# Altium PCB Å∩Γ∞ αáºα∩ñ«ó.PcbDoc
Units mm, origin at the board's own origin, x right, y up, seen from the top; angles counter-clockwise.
Board outline 100 x 65 mm, 2 copper layers (Top Layer, Bottom Layer); 171 components, 171 nets, 507 pads, 41 vias.
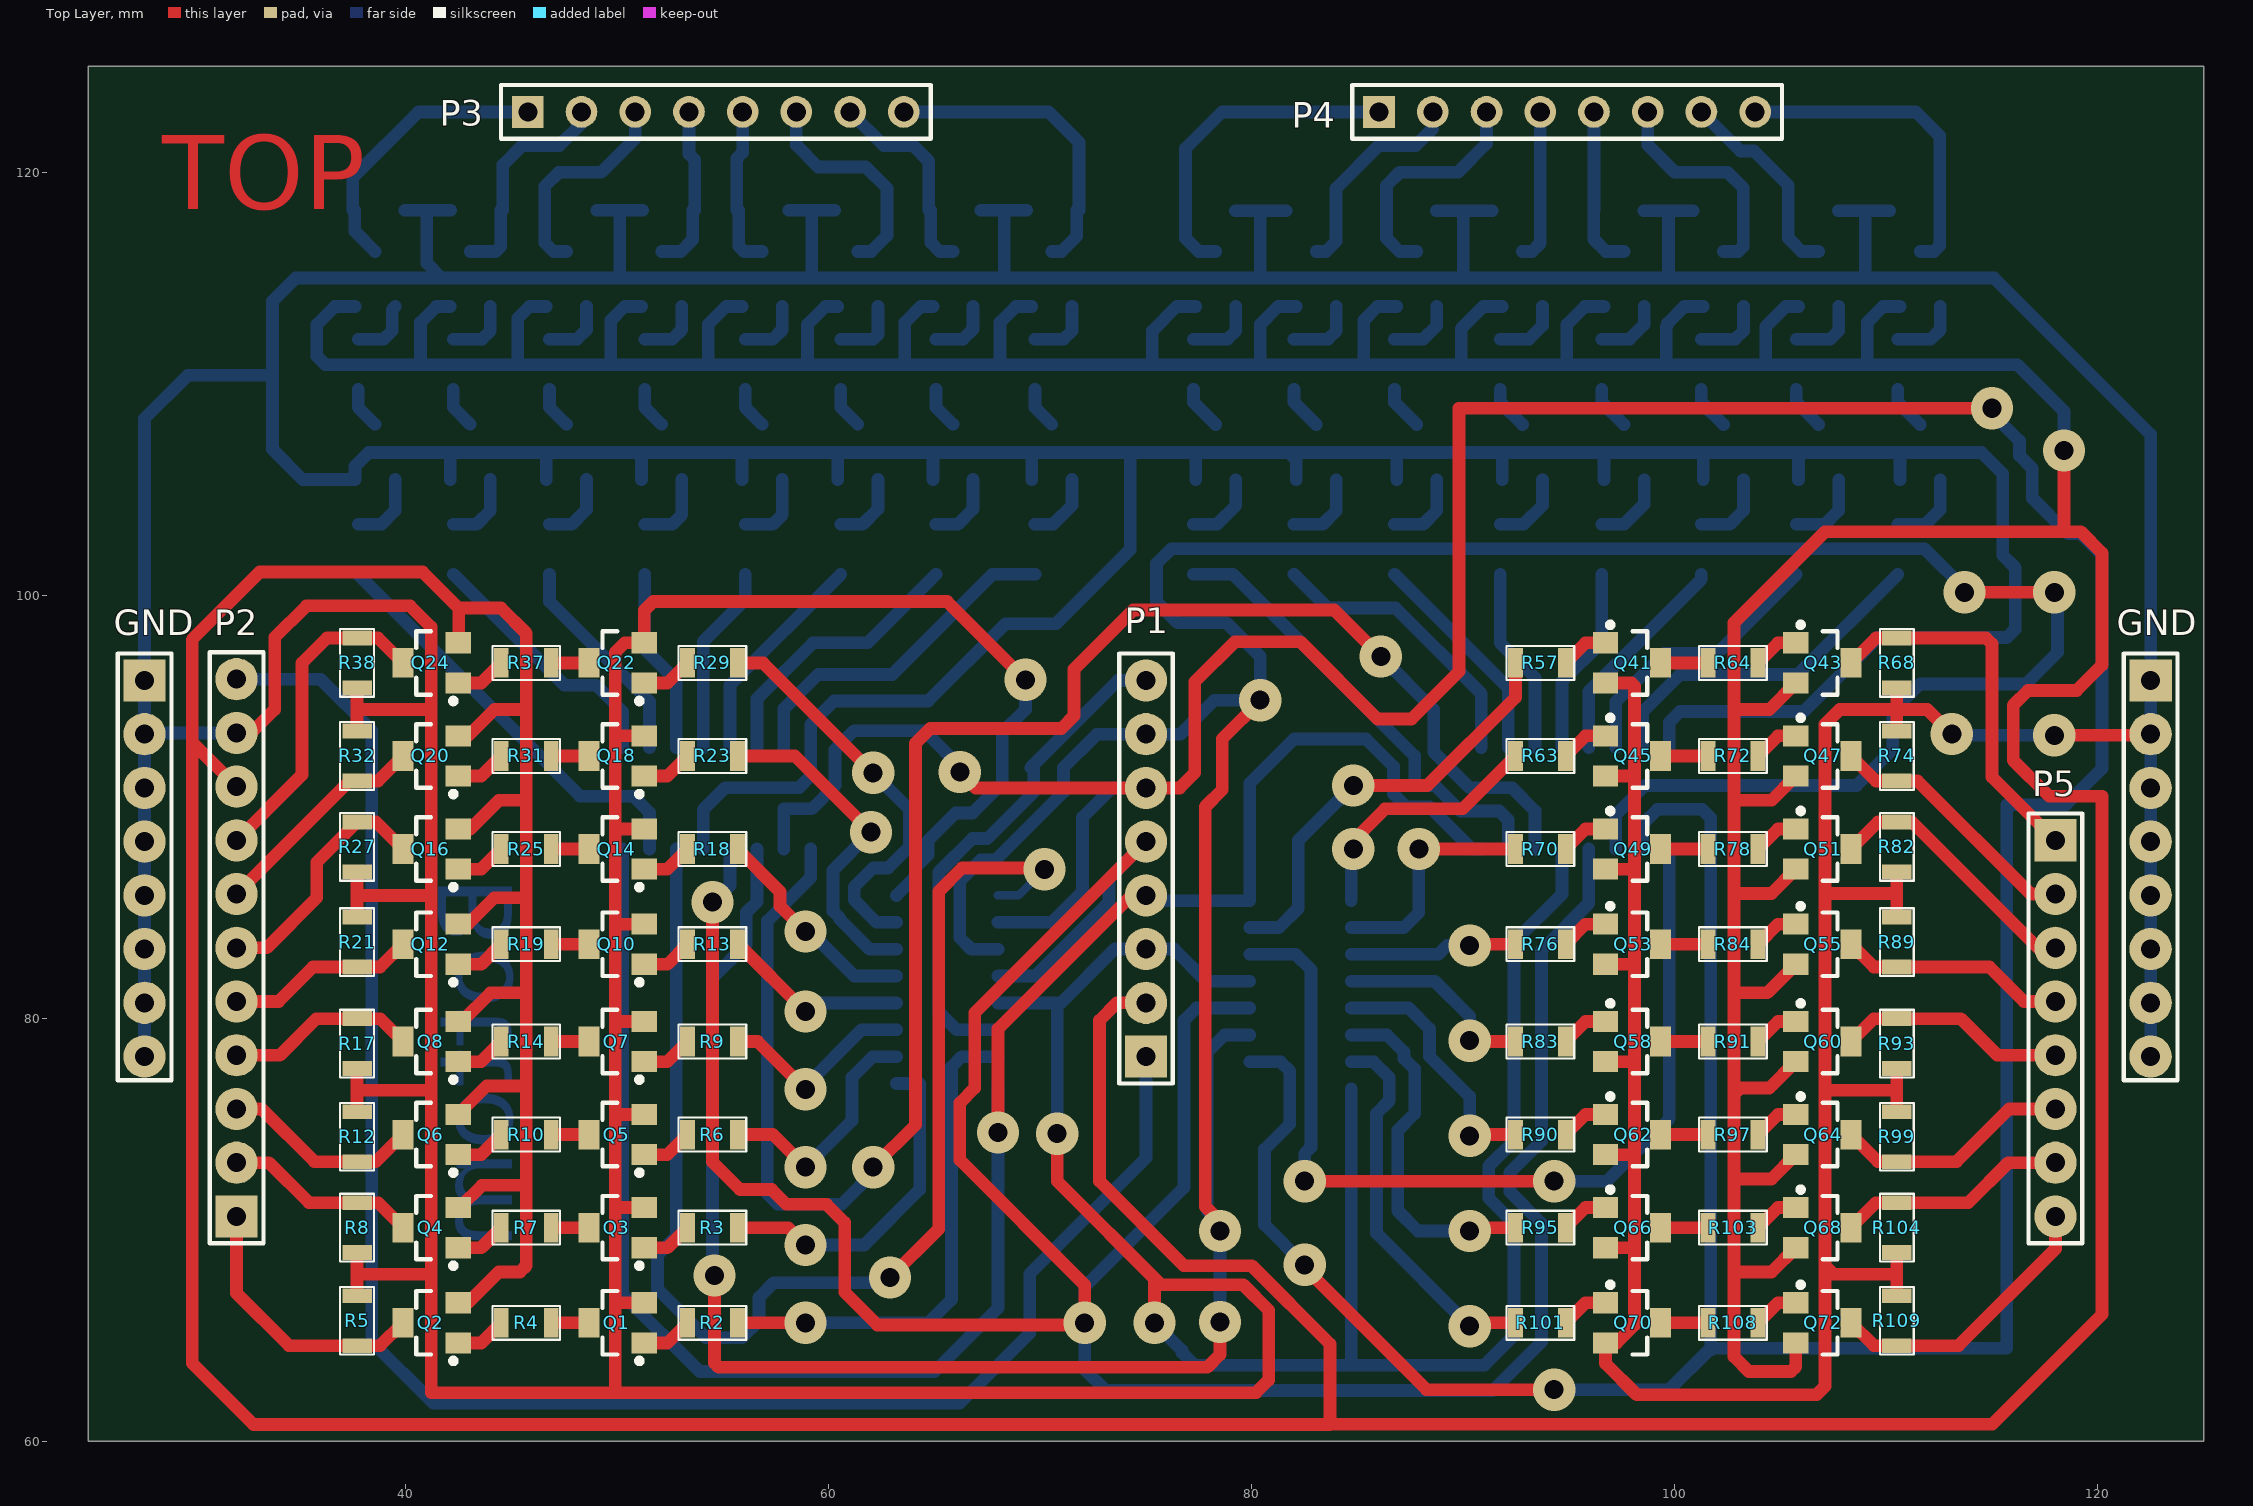
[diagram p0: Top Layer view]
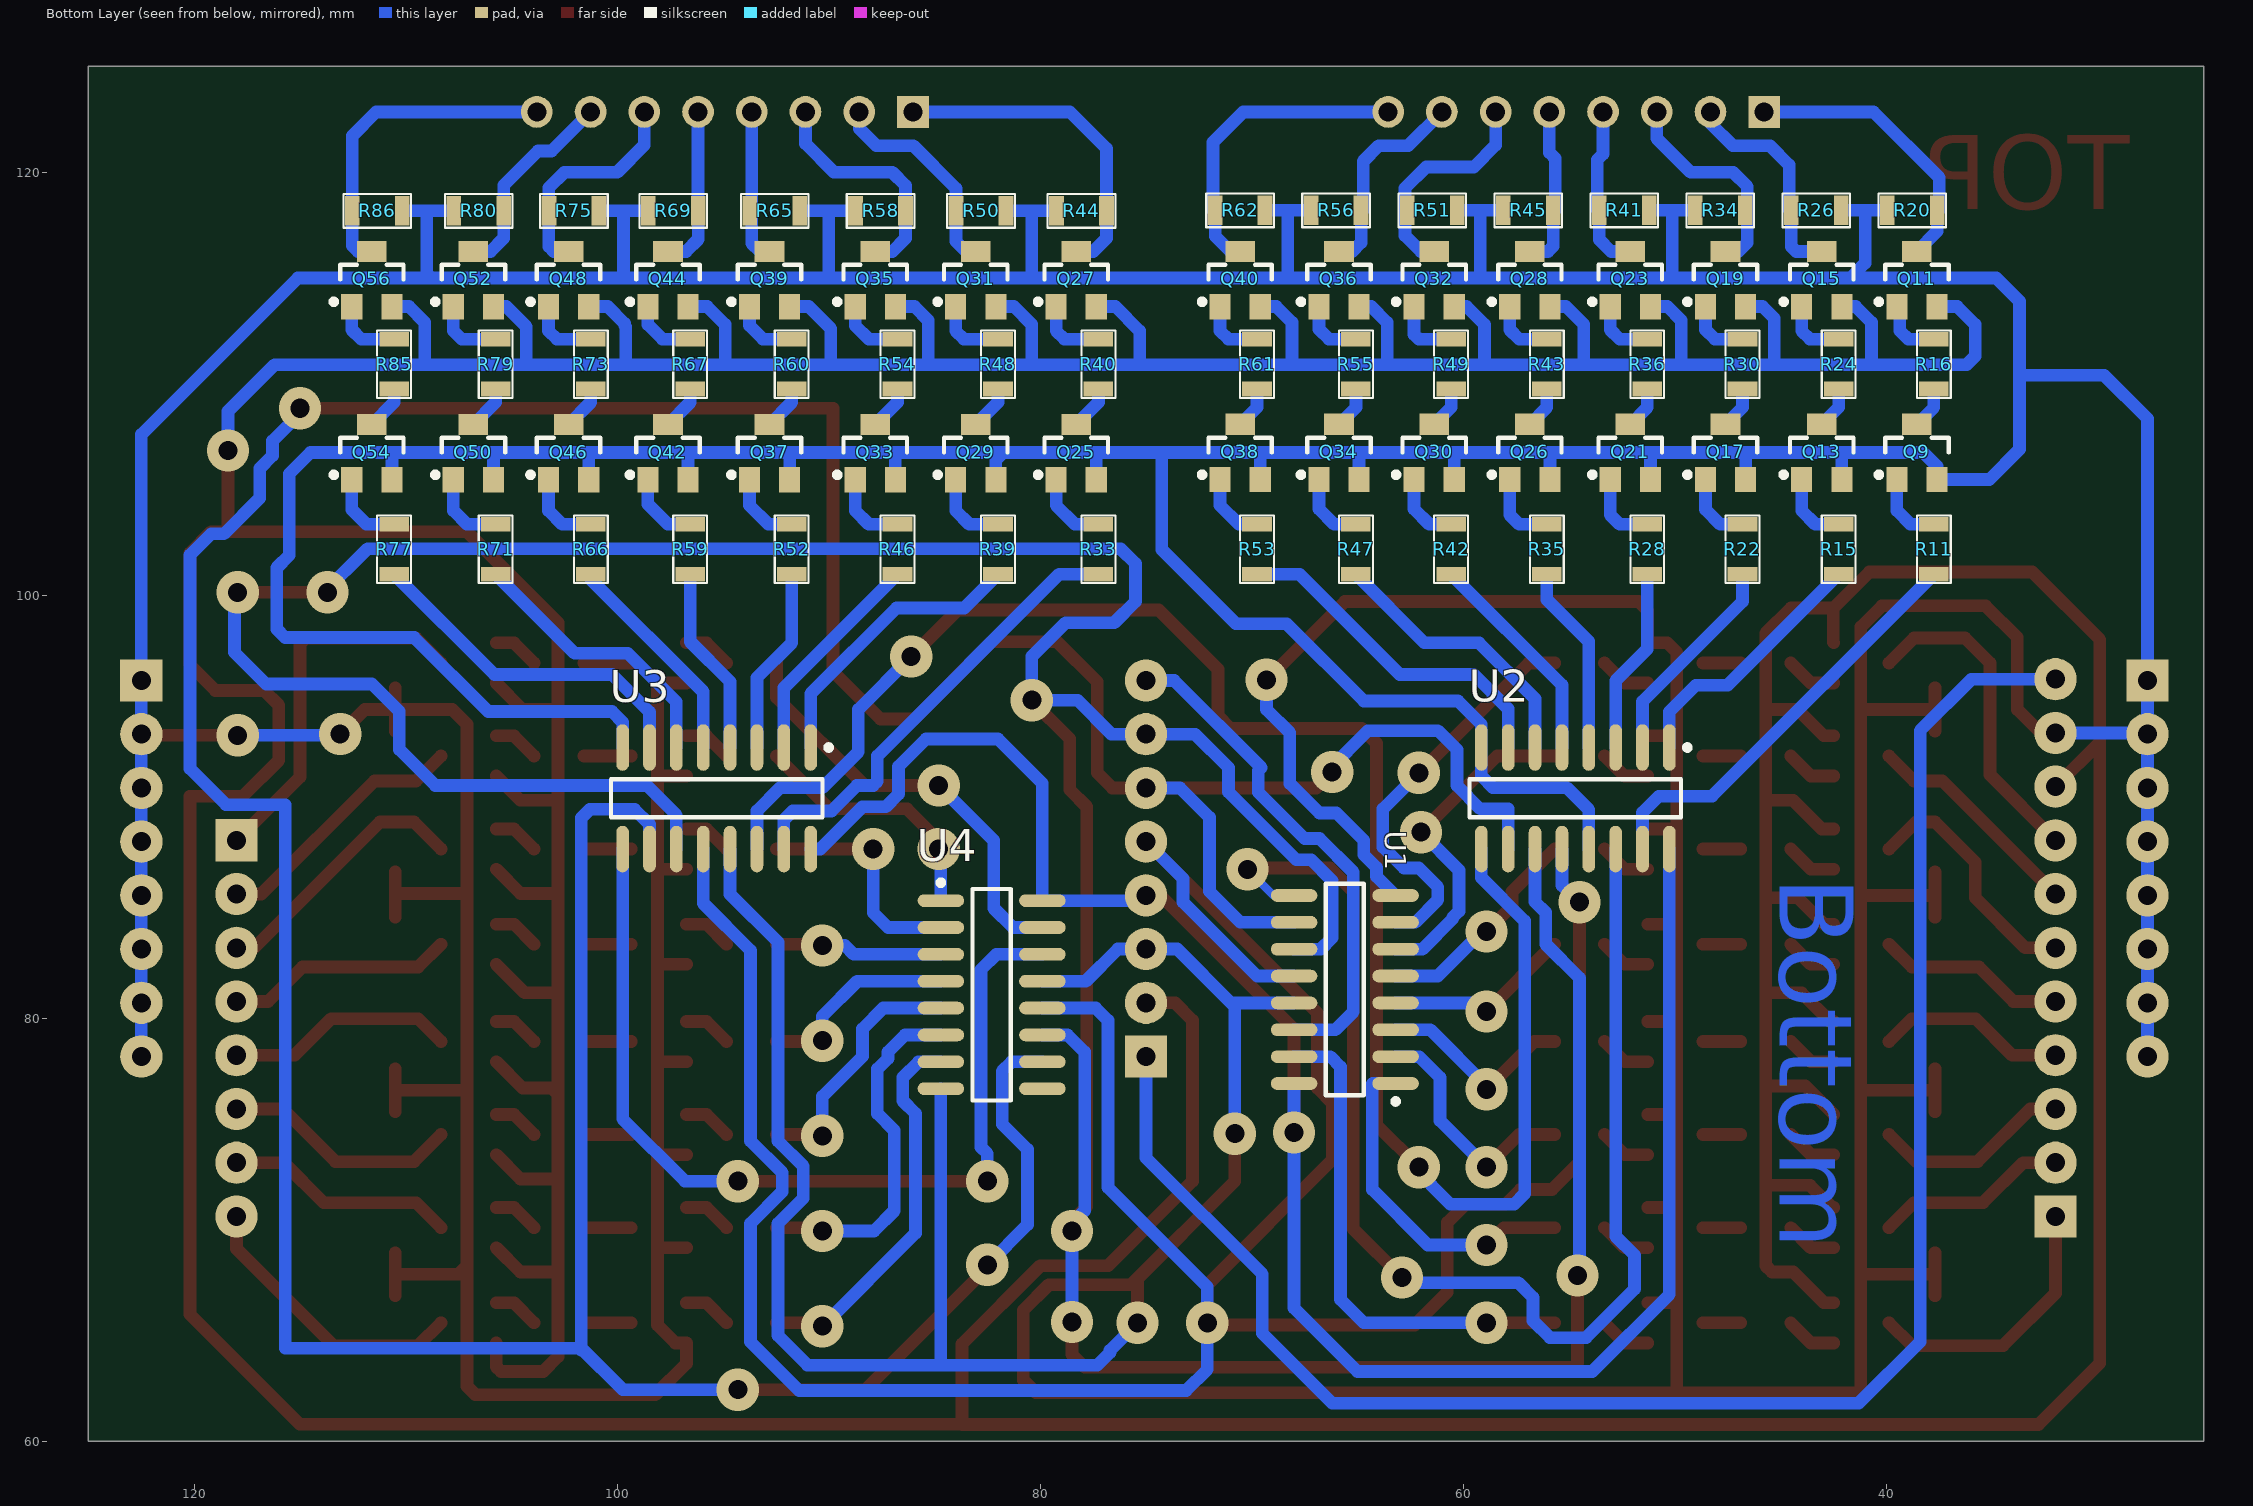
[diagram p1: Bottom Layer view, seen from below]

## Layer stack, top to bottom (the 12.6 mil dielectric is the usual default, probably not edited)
Top Solder: solder mask 0.0102, Solder Resist, Dk 3.5
Top Layer: signal copper 0.0356
Dielectric 1: dielectric 0.32, FR-4, Dk 4.8
Bottom Layer: signal copper 0.0356
Bottom Solder: solder mask 0.0102, Solder Resist, Dk 3.5

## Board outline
25,125 25,60 125,60 125,125

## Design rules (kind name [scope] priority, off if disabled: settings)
Clearance [All] p1: gap=0.3 ignorepadtopadclearanceinfootprint=FALSE except(0: Arc-Hole Track-Hole SMDPad-Hole THPad-Hole Via-Hole Fill-Hole Poly-Hole Region-Hole Text-Hole)
PolygonConnect [All] p1: connectstyle=Relief reliefconductorwidth=0.254 reliefentries=4 polygonreliefangle="90 Angle" airgapwidth=0.254
RoutingVias [All] p1: holewidth=0.711 width=1.27 viastyle="Through Hole" minholewidth=0.711 minwidth=1.27 maxholewidth=0.711 maxwidth=1.27
SolderMaskExpansion [All] p1: expansion=0.102
Width [All] p1: maxlimit=1 minlimit=0.4 preferedwidth=0.4 minimp=50.000000 maximp=50.000000 favimp=50.000000
30 further rules are at their usual default settings.

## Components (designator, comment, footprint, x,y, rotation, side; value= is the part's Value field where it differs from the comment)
GND "8pin" 8PIN 27.65,95.97 r270 top (schematic designator P3)
GND "8pin" 8PIN 122.5,95.97 r270 top (schematic designator P3)
P1 "Ещё порты" HDR1X8#1 75,78.19 r90 top
P2 "Ещё порты" HDR_X11 32,70.63 r90 top
P3 "Ещё порты" HDR1X8#2 45.77,122.85 r0 top
P4 "Ещё порты" HDR1X8#2 86.02,122.85 r0 top
P5 "Ещё порты" HDR1X8#1 118,88.41 r270 top
Q1 "2SC2712" SOT23_N 50,65.6 r180 top
Q2 "2SA1162" SOT23_N 41.2,65.6 r180 top
Q3 "2SC2712" SOT23_N 50,70.1 r180 top
Q4 "2SA1162" SOT23_N 41.2,70.1 r180 top
Q5 "2SC2712" SOT23_N 50,74.5 r180 top
Q6 "2SA1162" SOT23_N 41.2,74.5 r180 top
Q7 "2SC2712" SOT23_N 50,78.9 r180 top
Q8 "2SA1162" SOT23_N 41.2,78.9 r180 top
Q9 "2SC2712" SOT23_N 38.55,106.75 r90 bottom
Q10 "2SC2712" SOT23_N 50,83.5 r180 top
Q11 "2SA1162" SOT23_N 38.55,114.925 r90 bottom
Q12 "2SA1162" SOT23_N 41.2,83.5 r180 top
Q13 "2SC2712" SOT23_N 43.05,106.75 r90 bottom
Q14 "2SC2712" SOT23_N 50,88 r180 top
Q15 "2SA1162" SOT23_N 43.05,114.925 r90 bottom
Q16 "2SA1162" SOT23_N 41.2,88 r180 top
Q17 "2SC2712" SOT23_N 47.6,106.75 r90 bottom
Q18 "2SC2712" SOT23_N 50,92.4 r180 top
Q19 "2SA1162" SOT23_N 47.6,114.925 r90 bottom
Q20 "2SA1162" SOT23_N 41.2,92.4 r180 top
Q21 "2SC2712" SOT23_N 52.1,106.75 r90 bottom
Q22 "2SC2712" SOT23_N 50,96.8 r180 top
Q23 "2SA1162" SOT23_N 52.1,114.925 r90 bottom
Q24 "2SA1162" SOT23_N 41.2,96.8 r180 top
Q25 "2SC2712" SOT23_N 78.3,106.744 r90 bottom
Q26 "2SC2712" SOT23_N 56.85,106.75 r90 bottom
Q27 "2SA1162" SOT23_N 78.3,114.925 r90 bottom
Q28 "2SA1162" SOT23_N 56.85,114.925 r90 bottom
Q29 "2SC2712" SOT23_N 83.05,106.744 r90 bottom
Q30 "2SC2712" SOT23_N 61.375,106.75 r90 bottom
Q31 "2SA1162" SOT23_N 83.05,114.925 r90 bottom
Q32 "2SA1162" SOT23_N 61.375,114.925 r90 bottom
Q33 "2SC2712" SOT23_N 87.8,106.744 r90 bottom
Q34 "2SC2712" SOT23_N 65.875,106.75 r90 bottom
Q35 "2SA1162" SOT23_N 87.8,114.925 r90 bottom
Q36 "2SA1162" SOT23_N 65.875,114.925 r90 bottom
Q37 "2SC2712" SOT23_N 92.8,106.744 r90 bottom
Q38 "2SC2712" SOT23_N 70.55,106.75 r90 bottom
Q39 "2SA1162" SOT23_N 92.8,114.925 r90 bottom
Q40 "2SA1162" SOT23_N 70.55,114.925 r90 bottom
Q41 "2SC2712" SOT23_N 98,96.8 r0 top
Q42 "2SC2712" SOT23_N 97.6,106.744 r90 bottom
Q43 "2SA1162" SOT23_N 107,96.8 r0 top
Q44 "2SA1162" SOT23_N 97.6,114.925 r90 bottom
Q45 "2SC2712" SOT23_N 98,92.4 r0 top
Q46 "2SC2712" SOT23_N 102.3,106.744 r90 bottom
Q47 "2SA1162" SOT23_N 107,92.4 r0 top
Q48 "2SA1162" SOT23_N 102.3,114.925 r90 bottom
Q49 "2SC2712" SOT23_N 98,88 r0 top
Q50 "2SC2712" SOT23_N 106.8,106.744 r90 bottom
Q51 "2SA1162" SOT23_N 107,88 r0 top
Q52 "2SA1162" SOT23_N 106.8,114.925 r90 bottom
Q53 "2SC2712" SOT23_N 98,83.5 r0 top
Q54 "2SC2712" SOT23_N 111.6,106.744 r90 bottom
Q55 "2SA1162" SOT23_N 107,83.5 r0 top
Q56 "2SA1162" SOT23_N 111.6,114.925 r90 bottom
Q58 "2SC2712" SOT23_N 98,78.9 r0 top
Q60 "2SA1162" SOT23_N 107,78.9 r0 top
Q62 "2SC2712" SOT23_N 98,74.5 r0 top
Q64 "2SA1162" SOT23_N 107,74.5 r0 top
Q66 "2SC2712" SOT23_N 98,70.1 r0 top
Q68 "2SA1162" SOT23_N 107,70.1 r0 top
Q70 "2SC2712" SOT23_N 98,65.6 r0 top
Q72 "2SA1162" SOT23_N 107,65.6 r0 top
R2 "1k" 6-0805_N 54.5,65.6 r180 top
R3 "1k" 6-0805_N 54.5,70.1 r180 top
R4 "22k" 6-0805_N 45.7,65.6 r0 top
R5 "3k" 6-0805_N 37.7,65.7 r90 top
R6 "1k" 6-0805_N 54.5,74.5 r180 top
R7 "22k" 6-0805_N 45.7,70.1 r0 top
R8 "3k" 6-0805_N 37.7,70.1 r270 top
R9 "1k" 6-0805_N 54.5,78.9 r180 top
R10 "22k" 6-0805_N 45.7,74.5 r0 top
R11 "1k" 6-0805_N 37.75,102.175 r90 bottom
R12 "3k" 6-0805_N 37.7,74.4 r90 top
R13 "1k" 6-0805_N 54.5,83.5 r180 top
R14 "3k" 6-0805_N 45.7,78.9 r0 top
R15 "1k" 6-0805_N 42.25,102.175 r90 bottom
R16 "22k" 6-0805_N 37.75,110.925 r270 bottom
R17 "22k" 6-0805_N 37.7,78.8 r270 top
R18 "1k" 6-0805_N 54.5,88 r180 top
R19 "22k" 6-0805_N 45.7,83.5 r0 top
R20 "3k" 6-0805_N 38.769,118.2 r0 bottom
R21 "3k" 6-0805_N 37.7,83.6 r90 top
R22 "1k" 6-0805_N 46.8,102.175 r90 bottom
R23 "1k" 6-0805_N 54.5,92.4 r180 top
R24 "22k" 6-0805_N 42.25,110.925 r270 bottom
R25 "22k" 6-0805_N 45.7,88 r0 top
R26 "3k" 6-0805_N 43.309,118.2 r180 bottom
R27 "3k" 6-0805_N 37.7,88.1 r270 top
R28 "1k" 6-0805_N 51.3,102.175 r90 bottom
R29 "1k" 6-0805_N 54.5,96.8 r180 top
R30 "22k" 6-0805_N 46.8,110.925 r270 bottom
R31 "22k" 6-0805_N 45.7,92.4 r0 top
R32 "3k" 6-0805_N 37.7,92.4 r90 top
R33 "1k" 6-0805_N 77.25,102.175 r90 bottom
R34 "3k" 6-0805_N 47.849,118.2 r0 bottom
R35 "1k" 6-0805_N 56.05,102.175 r90 bottom
R36 "22k" 6-0805_N 51.3,110.925 r270 bottom
R37 "22k" 6-0805_N 45.7,96.8 r0 top
R38 "3k" 6-0805_N 37.7,96.8 r270 top
R39 "1k" 6-0805_N 82,102.175 r90 bottom
R40 "22k" 6-0805_N 77.25,110.925 r270 bottom
R41 "3k" 6-0805_N 52.389,118.2 r180 bottom
R42 "1k" 6-0805_N 60.575,102.175 r90 bottom
R43 "22k" 6-0805_N 56.05,110.925 r270 bottom
R44 "3k" 6-0805_N 78.05,118.175 r0 bottom
R45 "3k" 6-0805_N 56.93,118.2 r0 bottom
R46 "1k" 6-0805_N 86.75,102.175 r90 bottom
R47 "1k" 6-0805_N 65.075,102.175 r90 bottom
R48 "22k" 6-0805_N 82,110.925 r270 bottom
R49 "22k" 6-0805_N 60.575,110.925 r270 bottom
R50 "3k," 6-0805_N 82.8,118.175 r180 bottom
R51 "3k" 6-0805_N 61.47,118.2 r180 bottom
R52 "1k" 6-0805_N 91.75,102.175 r90 bottom
R53 "1k" 6-0805_N 69.75,102.175 r90 bottom
R54 "22k" 6-0805_N 86.75,110.925 r270 bottom
R55 "22k" 6-0805_N 65.075,110.925 r270 bottom
R56 "3k" 6-0805_N 66.01,118.2 r0 bottom
R57 "1k" 6-0805_N 93.65,96.8 r0 top
R58 "3k" 6-0805_N 87.55,118.175 r0 bottom
R59 "1k" 6-0805_N 96.55,102.175 r90 bottom
R60 "22k" 6-0805_N 91.75,110.925 r270 bottom
R61 "22k" 6-0805_N 69.75,110.925 r270 bottom
R62 "3k" 6-0805_N 70.55,118.2 r180 bottom
R63 "1k" 6-0805_N 93.65,92.4 r0 top
R64 "22k" 6-0805_N 102.75,96.8 r180 top
R65 "3k" 6-0805_N 92.55,118.175 r180 bottom
R66 "1k" 6-0805_N 101.25,102.175 r90 bottom
R67 "22k" 6-0805_N 96.55,110.925 r270 bottom locked
R68 "3k" 6-0805_N 110.5,96.8 r270 top
R69 "3k" 6-0805_N 97.35,118.175 r0 bottom
R70 "1k" 6-0805_N 93.65,88 r0 top
R71 "1k" 6-0805_N 105.75,102.175 r90 bottom
R72 "22k" 6-0805_N 102.75,92.4 r180 top
R73 "22k" 6-0805_N 101.25,110.925 r270 bottom
R74 "3k" 6-0805_N 110.5,92.4 r90 top
R75 "3k" 6-0805_N 102.05,118.175 r180 bottom
R76 "1k" 6-0805_N 93.65,83.5 r0 top
R77 "1k" 6-0805_N 110.55,102.175 r90 bottom
R78 "22k" 6-0805_N 102.75,88 r180 top
R79 "22k" 6-0805_N 105.75,110.925 r270 bottom
R80 "3k" 6-0805_N 106.55,118.175 r0 bottom
R82 "3k" 6-0805_N 110.5,88.1 r270 top
R83 "1k" 6-0805_N 93.65,78.9 r0 top
R84 "22k" 6-0805_N 102.75,83.5 r180 top
R85 "22k" 6-0805_N 110.55,110.925 r270 bottom
R86 "3k" 6-0805_N 111.35,118.175 r180 bottom
R89 "3k" 6-0805_N 110.5,83.6 r90 top
R90 "1k" 6-0805_N 93.65,74.5 r0 top
R91 "22k" 6-0805_N 102.75,78.9 r180 top
R93 "3k" 6-0805_N 110.5,78.8 r270 top
R95 "1k" 6-0805_N 93.65,70.1 r0 top
R97 "22k" 6-0805_N 102.75,74.5 r180 top
R99 "22k" 6-0805_N 110.5,74.4 r90 top
R101 "1k" 6-0805_N 93.65,65.6 r0 top
R103 "22k" 6-0805_N 102.75,70.1 r180 top
R104 "3k" 6-0805_N 110.5,70.1 r270 top
R108 "22k" 6-0805_N 102.75,65.6 r180 top
R109 "3k" 6-0805_N 110.5,65.7 r90 top
U1 "SN74HC595D" D016_N 65.6,81.36 r0 bottom
U2 "SN74HC595D" D016_N 54.7,90.4 r270 bottom
U3 "SN74HC595D" D016_N 95.3,90.4 r270 bottom
U4 "SN74HC595D" D016_N 82.3,81.115 r180 bottom

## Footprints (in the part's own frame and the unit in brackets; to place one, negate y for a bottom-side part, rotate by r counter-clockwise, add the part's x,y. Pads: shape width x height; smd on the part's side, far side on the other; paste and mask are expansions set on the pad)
6-0805_N [mm]
  rect 0.7x1.4 smd: 1(-1.181,0) 2(1.181,0)
  silkscreen extent -1.6,-0.8 1.6,0.8, body extent -1.07,-0.7 1.07,0.7, height 0.7
8PIN [mm] "Connector; Header; 4 Position"
  rect 2x2 hole 0.9: 1(0,0)
  round 2 hole 0.9: 2(2.54,0) 3(5.08,0) 4(7.62,0) 5(10.16,0) 6(12.7,0) 7(15.24,0) 8(17.78,0)
  silkscreen extent -1.27,-1.27 18.9,1.27
D016_N [mm]
  oval 2.2x0.6 smd: 1(-2.4,4.445) 2(-2.4,3.175) 3(-2.4,1.905) 4(-2.4,0.635) 5(-2.4,-0.635) 6(-2.4,-1.905) 7(-2.4,-3.175) 8(-2.4,-4.445) 9(2.4,-4.445) 10(2.4,-3.175) 11(2.4,-1.905) 12(2.4,-0.635) 13(2.4,0.635) 14(2.4,1.905) 15(2.4,3.175) 16(2.4,4.445)
  silkscreen extent -2.52,-5 0.9,5.42, body extent -1.95,-4.95 1.95,4.95, height 1.75
HDR1X8#1 [mm] "Connector; Header; 8 Position"
  rect 2x2 hole 0.9: 1(0,0)
  round 2 hole 0.9: 2(2.54,0) 3(5.08,0) 4(7.62,0) 5(10.16,0) 6(12.7,0) 7(15.24,0) 8(17.78,0)
  silkscreen extent -1.27,-1.27 19.05,1.27
HDR1X8#2 [mm] "Connector; Header; 8 Position"
  rect 1.5x1.5 hole 0.9: 1(0,0)
  round 1.5 hole 0.9: 2(2.54,0) 3(5.08,0) 4(7.62,0) 5(10.16,0) 6(12.7,0) 7(15.24,0) 8(17.78,0)
  silkscreen extent -1.27,-1.27 19.05,1.27
HDR_X11 [mm] "Connector; Header; 11 Position"
  rect 2x2 hole 0.9: 1(0,0)
  round 2 hole 0.9: 2(2.54,0) 3(5.08,0) 4(7.62,0) 5(10.16,0) 6(12.7,0) 7(15.24,0) 8(17.78,0) 9(20.32,0) 10(22.86,0) 11(25.4,0)
  silkscreen extent -1.27,-1.27 26.67,1.27
SOT23_N [mm]
  rect 1.2x1 smd: 1(-1.277,0.95) 2(-1.277,-0.95)
  rect 1x1.4 smd: 3(1.331,0)
  silkscreen extent -1.18,-1.5 0.7,1.92, body extent -0.7,-1.5 0.7,1.5, height 1.1

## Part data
P1 P3 P4 P5: library part "Header 9", "Header, 9-Pin"
P2: library part "Header 11", "Header, 11-Pin"
Q1 Q3 Q5 Q7 Q9 Q10 Q13 Q14 Q17 Q18 Q21 Q22 Q25 Q26 Q29 Q30 Q33 Q34 Q37 Q38 Q41 Q42 Q45 Q46 Q49 Q50 Q53 Q54 Q58 Q62 Q66 Q70: "NPN"
Q2 Q4 Q6 Q8 Q11 Q12 Q15 Q16 Q19 Q20 Q23 Q24 Q27 Q28 Q31 Q32 Q35 Q36 Q39 Q40 Q43 Q44 Q47 Q48 Q51 Q52 Q55 Q56 Q60 Q64 Q68 Q72: "PNP"
R5 R8 R12 R14 R20 R21 R26 R27 R32 R34 R38 R41 R44 R45 R50 R51 R56 R58 R62 R65 R68 R69 R74 R75 R80 R82 R86 R89 R93 R104 R109: library part 22k, "22k"
U1 U2 U3 U4: "8-Bit Shift Register with 3-State Output Registers"

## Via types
v1: diameter 2, hole 0.9, Top Layer to Bottom Layer, 41 vias

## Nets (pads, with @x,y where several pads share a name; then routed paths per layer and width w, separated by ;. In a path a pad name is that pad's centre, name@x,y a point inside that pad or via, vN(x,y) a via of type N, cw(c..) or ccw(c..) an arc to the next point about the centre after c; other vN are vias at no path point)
30V: P1.2 P2.9 Q2.2 Q4.2 Q6.2 Q8.2 Q11.2 Q12.2 Q15.2 Q16.2 Q19.2 Q20.2 Q23.2 Q24.2 Q27.2 Q28.2 Q31.2 Q32.2 Q35.2 Q36.2 Q39.2 Q40.2 Q43.2 Q44.2 Q47.2 Q48.2 Q51.2 Q52.2 Q55.2 Q56.2 Q60.2 Q64.2 Q68.2 Q72.2 | length 511.3
  Top Layer w0.6: P2.9 29.9,93.05 ; Q2.2 42.95,66.55 44.4,68 45.4,68 45.7,68.3 45.7,72.1 ; Q4.2 42.55,71.05 43.6,72.1 45.7,72.1 ; Q6.2 43.827,76.8 45.7,76.8 ; Q8.2 42.65,79.85 44,81.2 45.7,81.2 ; Q12.2 42.95,84.45 44.2,85.7 45.7,85.7 ; Q16.2 43.05,88.95 44.4,90.3 45.7,90.3 ; Q20.2 42.95,93.35 44.2,94.6 45.7,94.6 ; Q24.2 42.5,97.773 42.5,99.4 ; P1.2 73.63,80.73 72.8,79.9 72.8,72.3 76.8,68.3 80,68.3 83.7,64.6 83.7,60.8 ; Q72.2 105.723,63.523 105.5,63.3 103.5,63.3 102.8,64 102.8,68 ; Q68.2 104.573,68 102.8,68 ; Q64.2 104.573,72.4 102.8,72.4 ; Q60.2 104.473,76.7 103.1,76.7 102.8,76.4 ; Q55.2 104.373,81.2 102.8,81.2 ; Q51.2 104.573,85.9 102.8,85.9 ; Q47.2 104.573,90.3 102.8,90.3 ; Q43.2 104.473,94.6 102.8,94.6 ; v1(118.4,106.84) 118.4,103 ; 29.9,93.05 29.9,97.9 33.1,101.1 40.8,101.1 42.5,99.4 ; 29.9,93.05 29.9,63.7 32.806,60.794 83.7,60.794 83.7,60.8 ; 42.5,99.4 44.5,99.4 45.7,98.2 45.7,94.6 ; 45.7,72.1 45.7,76.8 ; 45.7,76.8 45.7,81.2 ; 45.7,81.2 45.7,85.7 ; 45.7,85.7 45.7,90.3 ; 45.7,90.3 45.7,94.6 ; 83.7,60.8 115,60.8 120.2,66 120.2,90.5 117.7,90.5 116,92.2 116,94.8 116.7,95.5 119,95.5 120.2,96.7 120.2,102 119.2,103 118.4,103 ; 102.8,68 102.8,72.4 ; 102.8,72.4 102.8,76.4 ; 102.8,76.4 102.8,81.2 ; 102.8,81.2 102.8,85.9 ; 102.8,85.9 102.8,90.3 ; 102.8,90.3 102.8,94.6 ; 102.8,94.6 102.8,98.7 107.1,103 118.4,103
  Bottom Layer w0.6: Q11.2 36.648,113.648 35.8,112.8 35.8,111.3 36.2,110.9 40.7,110.9 ; Q15.2 41.448,113.648 40.7,112.9 40.7,110.9 ; Q19.2 45.848,113.648 45.3,113.1 45.3,110.9 ; Q23.2 50.348,113.648 49.7,113 49.7,110.9 ; Q28.2 55.148,113.648 54.3,112.8 54.3,110.9 ; Q32.2 59.848,113.648 59,112.8 59,110.9 ; Q36.2 64.348,113.648 63.6,112.9 63.6,110.9 ; Q40.2 68.848,113.648 68.1,112.9 68.1,110.9 ; Q27.2 76.448,113.648 75.3,112.5 75.3,110.9 ; Q31.2 81.248,113.648 80.4,112.8 80.4,110.9 ; Q35.2 85.948,113.648 85.3,113 85.3,110.9 ; Q39.2 90.948,113.648 89.9,112.6 89.9,110.9 ; Q44.2 95.748,113.648 94.9,112.8 94.9,110.9 ; Q48.2 100.448,113.648 99.65,112.85 99.65,112.749 99.6,112.699 99.6,110.9 ; Q52.2 105.248,113.648 104.3,112.7 104.3,110.9 ; Q56.2 109.848,113.648 109.1,112.9 109.1,110.9 ; v1(118.4,106.84) 118.4,108.7 116.2,110.9 109.1,110.9 ; 40.7,110.9 45.3,110.9 ; 45.3,110.9 49.7,110.9 ; 49.7,110.9 54.3,110.9 ; 54.3,110.9 59,110.9 ; 59,110.9 63.6,110.9 ; 63.6,110.9 68.1,110.9 ; 68.1,110.9 75.3,110.9 ; 75.3,110.9 80.4,110.9 ; 80.4,110.9 85.3,110.9 ; 85.3,110.9 89.9,110.9 ; 89.9,110.9 94.9,110.9 ; 94.9,110.9 99.6,110.9 ; 99.6,110.9 104.3,110.9 ; 104.3,110.9 109.1,110.9
Glow_1: P1.1 P2.11 | length 85.3
  Bottom Layer w0.6: P2.11 35.97,96.03 38.4,93.6 38.4,64.7 41.3,61.8 66.2,61.8 69.5,65.1 69.5,67.9 75,73.4 P1.1
Glow_2: GND.1 GND.2 GND.3 GND.4 GND.5 GND.6 GND.7 GND.8 P1.3 P2.10 Q1.2 Q3.2 Q5.2 Q7.2 Q9.2 Q10.2 Q13.2 Q14.2 Q17.2 Q18.2 Q21.2 Q22.2 Q25.2 Q26.2 Q29.2 Q30.2 Q33.2 Q34.2 Q37.2 Q38.2 Q41.2 Q42.2 Q45.2 Q46.2 Q49.2 Q50.2 Q53.2 Q54.2 Q58.2 Q62.2 Q66.2 Q70.2 R5.2 R8.2 R12.2 R17.2 R20.2 R21.2 R26.2 R27.2 R32.2 R34.2 R38.2 R41.2 R44.2 R45.2 R50.2 R51.2 R56.2 R58.2 R62.2 R65.2 R68.2 R69.2 R74.2 R75.2 R80.2 R82.2 R86.2 R89.2 R93.2 R99.2 R104.2 R109.2 U1.8 U1.13 U2.8 U2.13 U3.8 U3.13 U4.8 U4.13 | length 787.8
  Top Layer w0.6: P2.10 32.69,93.49 33.8,94.6 33.8,98 35.3,99.5 40.2,99.5 41.2,98.5 41.2,85.8 ; R5.2 37.7,67.9 ; R8.2 37.7,67.9 ; R12.2 37.7,76.6 ; R17.2 37.7,76.6 ; R21.2 37.7,85.85 ; R27.2 37.7,85.85 ; R32.2 37.7,94.6 ; R38.2 37.7,94.6 ; 41.1,94.6 37.7,94.6 ; Q1.2 50.05,66.55 49.9,66.4 ; Q3.2 49.95,71.05 49.9,71.1 ; Q5.2 49.95,75.45 49.9,75.4 ; Q7.2 49.95,79.85 49.9,79.9 ; Q10.2 49.95,84.45 49.9,84.5 ; Q14.2 49.95,88.95 49.9,88.9 ; Q18.2 49.95,93.35 49.9,93.4 ; v1(69.3,96) 65.6,99.7 51.7,99.7 51.277,99.277 Q22.2 50.35,97.75 49.9,97.3 49.9,93.4 ; v1@70.8,74.5 70.8,72.3 75.7,67.4 79.6,67.4 80.8,66.2 80.8,62.9 80.2,62.3 49.9,62.3 ; v1(75.4,65.6) 75.4,67.6 ; Q66.2 97.95,69.15 98.1,69 ; Q62.2 98.05,73.55 98.1,73.6 ; Q58.2 98.05,77.95 98.1,77.9 ; Q53.2 98.05,82.55 98.1,82.5 ; Q49.2 98.05,87.05 98.1,87.1 ; Q45.2 98.05,91.45 98.1,91.4 ; Q41.2 97.95,95.85 98.1,95.7 98.1,91.4 ; R109.2 110.5,67.9 ; R104.2 110.5,67.9 ; R99.2 110.5,76.6 ; R93.2 110.5,76.6 ; R89.2 110.5,85.9 ; R82.2 110.5,85.9 ; R74.2 110.5,94.6 ; R68.2 110.5,94.6 ; v1(113.1,93.44) 111.94,94.6 110.5,94.6 ; v1(117.944,93.374) 122.444,93.374 GND.2@122.5,93.43 ; 37.7,67.9 41.1,67.9 41.2,68 ; 37.7,76.6 41.2,76.6 ; 37.7,85.85 37.75,85.8 41.2,85.8 ; 41.2,68 41.2,62.3 49.9,62.3 ; 41.2,68 41.2,76.6 ; 41.2,76.6 41.2,85.8 ; 49.9,62.3 49.9,66.4 ; 49.9,66.4 49.9,71.1 ; 49.9,71.1 49.9,75.4 ; 49.9,75.4 49.9,79.9 ; 49.9,79.9 49.9,84.5 ; 49.9,84.5 49.9,88.9 ; 49.9,88.9 49.9,93.4 ; 98.1,69 98.1,73.6 ; 98.1,69 98.1,65.5 97.25,64.65 Q70.2 96.723,63.677 98.2,62.2 106.7,62.2 107.1,62.6 107.1,68.3 ; 98.1,73.6 98.1,77.9 ; 98.1,77.9 98.1,82.5 ; 98.1,82.5 98.1,87.1 ; 98.1,87.1 98.1,91.4 ; 107.1,68.3 107.1,76.6 ; 107.1,68.3 107.5,67.9 110.5,67.9 ; 107.1,76.6 107.1,85.9 ; 107.1,76.6 110.5,76.6 ; 107.1,85.9 107.1,93.9 107.8,94.6 110.5,94.6 ; 107.1,85.9 110.5,85.9
  Bottom Layer w0.6: GND.8@27.65,78.19 27.65,80.73 27.65,83.27 27.65,85.81 27.65,88.35 27.65,90.89 GND.2@27.65,93.43 ; P2.10 27.71,93.49 GND.2@27.65,93.43 ; R20.2 41,118.2 ; Q13.2 42.1,106.6 42.25,106.75 ; R26.2 41,118.2 ; Q17.2 46.65,106.65 46.75,106.75 ; R34.2 50.119,118.2 ; Q21.2 51.15,106.6 51,106.75 ; R41.2 50.119,118.2 ; U2.13 54.065,89.865 55.1,90.9 58.6,90.9 59.145,91.445 U2.8 59.145,93.895 60.25,95 64.7,95 68.35,98.65 70.75,98.65 74.25,102.15 74.25,106.75 ; Q26.2 55.9,106.65 56,106.75 ; R45.2 59.2,118.2 ; R51.2 59.2,118.2 ; Q30.2 60.425,106.675 60.5,106.75 ; U1.8 64.1,86.705 64.1,87.127 64.7,87.727 64.7,88.4 66,89.7 66.8,89.7 68.2,91.1 68.2,93.5 69.3,94.6 v1@69.3,95.8 ; Q34.2 64.925,106.575 64.75,106.75 ; R56.2 68.3,118.2 ; U1.13 70.975,80.725 ; R62.2 68.3,118.2 ; Q38.2 69.6,106.65 69.5,106.75 ; v1(70.8,74.54) 70.8,80.55 70.975,80.725 ; v1(75.4,65.6) 76.7,64.3 76.7,64.2 77.3,63.6 84.9,63.6 ; Q25.2 77.35,106.6 77.5,106.75 ; R44.2 80.4,118.175 ; U4.13 77.85,81.75 76.33,83.27 P1.3 73.52,83.27 70.975,80.725 ; R50.2 80.4,118.175 ; Q29.2 82.1,106.4 81.75,106.75 ; U4.8 84.7,63.8 84.9,63.6 ; Q33.2 86.85,106.6 87,106.75 ; R58.2 90,118.175 ; R65.2 90,118.175 ; Q37.2 91.85,106.6 92,106.75 ; U3.13 94.665,85.865 92.4,83.6 92.4,74.2 91.2,73 91.2,71.5 92.4,70.3 92.4,65 91,63.6 84.9,63.6 ; Q42.2 96.65,106.6 96.5,106.75 ; R69.2 99.7,118.175 ; U3.8 99.745,93.995 100.25,94.5 106.1,94.5 109.6,98 115.7,98 116.1,98.4 116.1,101.3 115.5,101.9 115.5,105.75 114.5,106.75 110.5,106.75 ; R75.2 99.7,118.175 ; Q46.2 101.35,106.65 101.25,106.75 ; Q50.2 105.85,106.6 106,106.75 ; R80.2 109,118.175 ; R86.2 109,118.175 ; Q54.2 110.65,106.6 110.5,106.75 ; v1@113.3,93.374 v1(117.944,93.374) ; GND.8@122.5,78.19 122.5,80.73 122.5,83.27 122.5,85.81 122.5,88.35 122.5,90.89 122.5,93.43 122.5,95.97 122.5,107.6 115.1,115 108.8,115 ; GND.2@27.65,93.43 27.65,95.97 27.65,108.35 29.7,110.4 33.7,110.4 ; 33.7,110.4 33.7,113.9 34.8,115 41.7,115 ; 33.7,110.4 33.7,106.9 35.127,105.473 Q9.2 37.6,106.1 38.25,106.75 42.25,106.75 ; 41,118.2 41,115.7 41.7,115 ; 41.7,115 50.2,115 ; 42.25,106.75 46.75,106.75 ; 46.75,106.75 51,106.75 ; 50.119,118.2 50.119,115.081 50.2,115 ; 50.2,115 59.2,115 ; 51,106.75 56,106.75 ; 56,106.75 60.5,106.75 ; 59.2,115 68.3,115 ; 59.2,115 59.2,118.2 ; 60.5,106.75 64.75,106.75 ; 64.75,106.75 69.5,106.75 ; 68.3,115 80.3,115 ; 68.3,115 68.3,118.2 ; 69.5,106.75 74.25,106.75 ; 74.25,106.75 77.5,106.75 ; 77.5,106.75 81.75,106.75 ; 80.3,115 90,115 ; 80.3,115 80.4,115.1 80.4,118.175 ; 81.75,106.75 87,106.75 ; 87,106.75 92,106.75 ; 90,115 99.7,115 ; 90,115 90,118.175 ; 92,106.75 96.5,106.75 ; 96.5,106.75 101.25,106.75 ; 99.7,115 108.8,115 ; 99.7,115 99.7,118.175 ; 101.25,106.75 106,106.75 ; 106,106.75 110.5,106.75 ; 108.8,115 109,115.2 109,118.175
L1_A: P2.1 Q2.3 R5.1 | length 13
  Top Layer w0.6: P2.1 32,67 34.481,64.519 R5.1 38.788,64.519 Q2.3
L1_B: P2.2 Q4.3 R8.1 | length 9.1
  Top Layer w0.6: P2.2 33.53,73.17 35.419,71.281 R8.1 38.688,71.281 Q4.3
L1_C: P2.3 Q6.3 R12.1 | length 9.4
  Top Layer w0.6: P2.3 33.19,75.71 35.681,73.219 R12.1 38.588,73.219 Q6.3
L1_D: P2.4 Q8.3 R17.1 | length 9
  Top Layer w0.6: P2.4 34.05,78.25 35.781,79.981 R17.1 38.788,79.981 Q8.3
L1_E: P2.5 Q12.3 R21.1 | length 9
  Top Layer w0.6: P2.5 33.99,80.79 35.619,82.419 R21.1 38.788,82.419 Q12.3
L1_F: P2.6 Q16.3 R27.1 | length 11.8
  Top Layer w0.6: P2.6 33.43,83.33 35.8,85.7 35.8,87.381 R27.1 38.588,89.281 Q16.3
L1_G: P2.7 Q20.3 R32.1 | length 10.6
  Top Layer w0.6: P2.7 37.349,91.219 R32.1 38.688,91.219 Q20.3
L1_H: P2.8 Q24.3 R38.1 | length 15.4
  Top Layer w0.6: P2.8 35.1,91.51 35.1,96.8 36.281,97.981 R38.1 38.688,97.981 Q24.3
L2_A: P3.1 Q11.3 R20.1 | length 13.5
  Bottom Layer w0.6: R20.1@37.488,118.2 37.488,119.738 40.6,122.85 P3.1 ; R20.1 37.588,117.218 Q11.3
L2_B: P3.2 Q15.3 R26.1 | length 10.5
  Bottom Layer w0.6: Q15.3 44.256,116.256 44.49,116.49 R26.1 ; R26.1@44.59,118.2 44.59,120.34 45.5,121.25 47.25,121.25 48.31,122.31 P3.2
L2_C: P3.3 Q19.3 R34.1 | length 10.3
  Bottom Layer w0.6: Q19.3 46.994,116.256 46.568,116.682 46.568,119.318 47.25,120 49.25,120 50.85,121.6 P3.3
L2_D: P3.4 Q23.3 R41.1 | length 7.8
  Bottom Layer w0.6: Q23.3 53.006,116.256 53.57,116.82 R41.1 ; P3.4 53.39,120.86 53.67,120.58 R41.1@53.67,118.2
L2_E: P3.5 Q28.3 R45.1 | length 7.7
  Bottom Layer w0.6: R45.1@55.649,118.2 55.649,120.649 55.93,120.93 P3.5 ; R45.1 55.749,116.501 55.994,116.256 Q28.3
L2_F: P3.6 Q32.3 R51.1 | length 10.6
  Bottom Layer w0.6: P3.6 58.47,121.28 59.5,120.25 61.75,120.25 62.751,119.249 62.751,117.001 62.006,116.256 Q32.3
L2_G: P3.7 Q36.3 R56.1 | length 9.8
  Bottom Layer w0.6: P3.7 62.61,121.25 64,121.25 64.729,120.521 R56.1@64.729,118.2 ; R56.1 64.829,116.671 65.244,116.256 Q36.3
L2_H: P3.8 Q40.3 R62.1 | length 14.8
  Bottom Layer w0.6: P3.8 70.4,122.85 71.831,121.419 R62.1@71.831,118.2 ; Q40.3 71.006,116.256 71.731,116.981 R62.1
L3_A: P4.1 Q27.3 R44.1 | length 15.8
  Bottom Layer w0.6: Q27.3 77.494,116.256 76.869,116.881 R44.1 76.869,121.119 78.6,122.85 P4.1
L3_B: P4.2 Q31.3 R50.1 | length 10.2
  Bottom Layer w0.6: Q31.3 83.506,116.256 83.981,116.731 R50.1 83.981,119.231 86,121.25 87.75,121.25 88.56,122.06 P4.2
L3_C: P4.3 Q35.3 R58.1 | length 11.2
  Bottom Layer w0.6: Q35.3 86.994,116.256 86.369,116.881 R58.1 86.369,119.369 87,120 89.75,120 91.1,121.35 P4.3
L3_D: P4.4 Q39.3 R65.1 | length 7.2
  Bottom Layer w0.6: Q39.3 93.256,116.256 93.64,116.64 P4.4
L3_E: P4.5 Q44.3 R69.1 | length 7.7
  Bottom Layer w0.6: P4.5 96.18,118.186 R69.1 96.169,116.831 96.744,116.256 Q44.3
L3_F: P4.6 Q48.3 R75.1 | length 10.7
  Bottom Layer w0.6: P4.6 98.72,121.28 100,120 102.5,120 103.231,119.269 R75.1 103.231,116.481 103.006,116.256 Q48.3
L3_G: P4.7 Q52.3 R80.1 | length 9.7
  Bottom Layer w0.6: P4.7 103.11,121 103.75,121 105.369,119.381 R80.1 105.369,116.881 105.994,116.256 Q52.3
L3_H: P4.8 Q56.3 R86.1 | length 15.4
  Bottom Layer w0.6: P4.8 111.4,122.85 112.531,121.719 R86.1 112.531,116.531 112.256,116.256 Q56.3
L4_A: P5.1 Q43.3 R68.1 | length 17.8
  Top Layer w0.6: Q43.3 109.512,97.981 R68.1 114.719,97.981 115,97.7 115,91.41 P5.1
L4_B: P5.2 Q47.3 R74.1 | length 12.4
  Top Layer w0.6: Q47.3 109.512,91.219 R74.1 111.481,91.219 116.83,85.87 P5.2
L4_C: P5.3 Q51.3 R82.1 | length 12.7
  Top Layer w0.6: Q51.3 109.612,89.281 R82.1 111.219,89.281 117.17,83.33 P5.3
L4_D: P5.4 Q55.3 R89.1 | length 10.8
  Top Layer w0.6: Q55.3 109.412,82.419 R89.1 114.881,82.419 116.51,80.79 P5.4
L4_E: P5.5 Q60.3 R93.1 | length 10.8
  Top Layer w0.6: Q60.3 109.412,79.981 R93.1 113.519,79.981 115.25,78.25 P5.5
L4_F: P5.6 Q64.3 R99.1 | length 11.2
  Top Layer w0.6: Q64.3 109.612,73.219 R99.1 113.319,73.219 115.81,75.71 P5.6
L4_G: P5.7 Q68.3 R104.1 | length 10.9
  Top Layer w0.6: Q68.3 109.512,71.281 R104.1 113.881,71.281 115.77,73.17 P5.7
L4_H: P5.8 Q72.3 R109.1 | length 13.5
  Top Layer w0.6: Q72.3 109.412,64.519 R109.1 113.419,64.519 118,69.1 P5.8
NetP1_5: P1.5 U1.12 U2.12 U3.12 U4.12 | length 147.1
  Top Layer w0.6: v1@54.5,85.4 54.5,73.2 55.8,71.9 57.3,71.9 58,71.2 59.9,71.2 60.75,70.35 60.75,67.05 62.3,65.5 71.9,65.5 72.1,65.7 72.1,67.4 66.2,73.3 66.2,76 66.9,76.7 66.9,80.25 P1.5
  Bottom Layer w0.6: v1@54.5,85.44 55.335,86.275 U2.12 ; U1.12 69.745,81.995 73.25,85.5 73.25,86.6 P1.5 ; U4.12 77.38,80.48 76.8,79.9 76.8,72 72.1,67.3 72.1,63.4 73.1,62.4 91.4,62.4 93.7,64.7 93.7,70.3 92.2,71.8 92.2,72.7 93.7,74.2 93.7,83.2 95.935,85.435 U3.12
  other v1: 72.1,65.6 54.5,85.49
NetP1_6: P1.6 U1.10 U2.10 U3.10 U4.10 | length 224.2
  Top Layer w0.6: v1(66.2,91.64) 66.95,90.89 P1.6 76.59,90.89 77.3,91.6 77.3,95.9 79.2,97.8 82.3,97.8 85.95,94.15 87.55,94.15 89.8,96.4 89.8,108.84 v1(115,108.84) ; v1@82.4,67.9 82.8,67.9 88.26,62.44 v1(94.3,62.44)
  Bottom Layer w0.6: U2.10 57.875,89.9 59.2,89.9 60.3,91 60.3,92.7 61.2,93.6 64.5,93.6 v1@66.4,91.7 ; U1.10 70.535,84.535 72,86 72,89.5 73.39,90.89 P1.6 ; U4.10 81.36,77.94 81.8,77.5 81.8,75 80.6,73.8 80.6,70.24 v1(82.5,68.34) ; v1(94.3,62.44) 99.74,62.44 101.7,64.4 ; U3.10 98.475,89.175 99.175,89.875 101.3,89.875 101.7,89.475 101.7,64.4 ; 101.7,64.3 101.7,64.4 ; v1@114.8,108.8 116.3,107.3 116.3,106.6 116.9,106 116.9,104.6 118.6,102.9 119.2,102.9 120.2,101.9 120.2,91.8 118.5,90.1 115.7,90.1 115.7,64.4 101.7,64.4
NetP1_7: P1.7 U1.11 U2.11 U3.11 U4.11 | length 200.1
  Top Layer w0.6: v1(54.6,67.84) 54.6,63.7 54.8,63.5 77.9,63.5 78.5,64.1 v1(78.5,65.64) ; v1(78.5,69.94) 78.5,70.4 77.8,71.1 77.8,90 78.6,90.8 78.6,93.2 v1@80.4,95 ; v1(113.7,100.14) v1(117.944,100.14)
  Bottom Layer w0.6: v1@54.9,67.9 54.5,68.3 54.5,81.9 56.1,83.5 56.1,85 56.605,85.505 U2.11 ; U1.11 66.735,83.265 66.2,83.8 66.2,86.5 67.2,87.5 67.9,87.5 71.1,90.7 71.1,91.85 72.68,93.43 P1.7 76.63,93.43 78.24,95.04 v1(80.4,95.04) 80.4,97.1 78.8,98.7 76.5,98.7 75.5,99.7 75.5,101.5 76.2,102.2 111.8,102.2 v1@113.95,100.05 ; v1@78.5,65.5 v1(78.5,65.64) v1(78.5,69.94) ; v1@78.8,69.6 79,69.8 77.9,70.9 77.9,78.4 78.71,79.21 U4.11 ; U3.11 97.205,89.605 98.6,91 108.6,91 110.3,92.7 110.3,94.5 111.6,95.8 116.6,95.8 118.1,97.3 v1@118.1,100.2
NetP1_8: P1.8 U1.14 | length 24.2
  Bottom Layer w0.6: U1.14 66.045,79.455 65.2,80.3 65.2,86.9 66.8,88.5 67.5,88.5 69.7,90.7 69.7,91.7 69.55,91.85 73.67,95.97 P1.8
NetQ1_1: Q1.1 R2.2 | length 2.4
  Top Layer w0.6: Q1.1 52.369,64.65 R2.2
NetQ1_3: Q1.3 R4.2 | length 1.8
  Top Layer w0.6: R4.2 Q1.3
NetQ2_1: Q2.1 R4.1 | length 2.4
  Top Layer w0.6: Q2.1 43.569,64.65 R4.1
NetQ3_1: Q3.1 R3.2 | length 2.4
  Top Layer w0.6: Q3.1 52.369,69.15 R3.2
NetQ3_3: Q3.3 R7.2 | length 1.8
  Top Layer w0.6: R7.2 Q3.3
NetQ4_1: Q4.1 R7.1 | length 2.4
  Top Layer w0.6: Q4.1 43.569,69.15 R7.1
NetQ5_1: Q5.1 R6.2 | length 2.4
  Top Layer w0.6: Q5.1 52.369,73.55 R6.2
NetQ5_3: Q5.3 R10.2 | length 1.8
  Top Layer w0.6: R10.2 Q5.3
NetQ6_1: Q6.1 R10.1 | length 2.4
  Top Layer w0.6: Q6.1 43.569,73.55 R10.1
NetQ7_1: Q7.1 R9.2 | length 2.4
  Top Layer w0.6: Q7.1 52.369,77.95 R9.2
NetQ7_3: Q7.3 R14.2 | length 1.8
  Top Layer w0.6: R14.2 Q7.3
NetQ8_1: Q8.1 R14.1 | length 2.4
  Top Layer w0.6: Q8.1 43.569,77.95 R14.1
NetQ9_1: Q9.1 R11.2 | length 3.5
  Bottom Layer w0.6: R11.2 38.856,103.356 39.5,104 Q9.1
NetQ9_3: Q9.3 R16.2 | length 2
  Bottom Layer w0.6: R16.2 37.75,108.881 Q9.3
NetQ10_1: Q10.1 R13.2 | length 2.4
  Top Layer w0.6: Q10.1 52.369,82.55 R13.2
NetQ10_3: Q10.3 R19.2 | length 1.8
  Top Layer w0.6: R19.2 Q10.3
NetQ11_1: Q11.1 R16.1 | length 3
  Bottom Layer w0.6: R16.1 38.962,112.106 39.356,112.5 39.356,113.504 Q11.1
NetQ12_1: Q12.1 R19.1 | length 2.4
  Top Layer w0.6: Q12.1 43.569,82.55 R19.1
NetQ13_1: Q13.1 R15.2 | length 3.5
  Bottom Layer w0.6: R15.2 43.356,103.356 44,104 Q13.1
NetQ13_3: Q13.3 R24.2 | length 2
  Bottom Layer w0.6: R24.2 42.25,108.881 Q13.3
NetQ14_1: Q14.1 R18.2 | length 2.4
  Top Layer w0.6: Q14.1 52.369,87.05 R18.2
NetQ14_3: Q14.3 R25.2 | length 1.8
  Top Layer w0.6: R25.2 Q14.3
NetQ15_1: Q15.1 R24.1 | length 3.1
  Bottom Layer w0.6: R24.1 43.606,112.106 44,112.5 Q15.1
NetQ16_1: Q16.1 R25.1 | length 2.4
  Top Layer w0.6: Q16.1 43.569,87.05 R25.1
NetQ17_1: Q17.1 R22.2 | length 3.5
  Bottom Layer w0.6: R22.2 47.856,103.356 48.55,104.05 Q17.1
NetQ17_3: Q17.3 R30.2 | length 2
  Bottom Layer w0.6: R30.2 46.8,108.881 Q17.3
NetQ18_1: Q18.1 R23.2 | length 2.4
  Top Layer w0.6: Q18.1 52.369,91.45 R23.2
NetQ18_3: Q18.3 R31.2 | length 1.8
  Top Layer w0.6: R31.2 Q18.3
NetQ19_1: Q19.1 R30.1 | length 3
  Bottom Layer w0.6: R30.1 48.106,112.106 48.55,112.55 Q19.1
NetQ20_1: Q20.1 R31.1 | length 2.4
  Top Layer w0.6: Q20.1 43.569,91.45 R31.1
NetQ21_1: Q21.1 R28.2 | length 3.6
  Bottom Layer w0.6: R28.2 52.606,103.356 53.05,103.8 Q21.1
NetQ21_3: Q21.3 R36.2 | length 2
  Bottom Layer w0.6: R36.2 51.3,108.881 Q21.3
NetQ22_1: Q22.1 R29.2 | length 2.4
  Top Layer w0.6: Q22.1 52.369,95.85 R29.2
NetQ22_3: Q22.3 R37.2 | length 1.8
  Top Layer w0.6: R37.2 Q22.3
NetQ23_1: Q23.1 R36.1 | length 3
  Bottom Layer w0.6: R36.1 52.606,112.106 53.05,112.55 Q23.1
NetQ24_1: Q24.1 R37.1 | length 2.4
  Top Layer w0.6: Q24.1 43.569,95.85 R37.1
NetQ25_1: Q25.1 R33.2 | length 3.6
  Bottom Layer w0.6: R33.2 78.356,103.356 79.25,104.25 Q25.1
NetQ25_3: Q25.3 R40.2 | length 2.1
  Bottom Layer w0.6: R40.2 77.25,109.125 Q25.3
NetQ26_1: Q26.1 R35.2 | length 3.6
  Bottom Layer w0.6: R35.2 57.356,103.356 57.8,103.8 Q26.1
NetQ26_3: Q26.3 R43.2 | length 2
  Bottom Layer w0.6: R43.2 56.05,108.881 Q26.3
NetQ27_1: Q27.1 R40.1 | length 3.3
  Bottom Layer w0.6: R40.1 78.856,112.106 79.25,112.5 Q27.1
NetQ28_1: Q28.1 R43.1 | length 3
  Bottom Layer w0.6: R43.1 57.356,112.106 57.8,112.55 Q28.1
NetQ29_1: Q29.1 R39.2 | length 3.7
  Bottom Layer w0.6: R39.2 83.356,103.356 84,104 Q29.1
NetQ29_3: Q29.3 R48.2 | length 2.1
  Bottom Layer w0.6: R48.2 82,109.125 Q29.3
NetQ30_1: Q30.1 R42.2 | length 3.4
  Bottom Layer w0.6: R42.2 61.606,103.356 62.325,104.075 Q30.1
NetQ30_3: Q30.3 R49.2 | length 2
  Bottom Layer w0.6: R49.2 60.575,108.881 Q30.3
NetQ31_1: Q31.1 R48.1 | length 3.3
  Bottom Layer w0.6: R48.1 83.606,112.106 84,112.5 Q31.1
NetQ32_1: Q32.1 R49.1 | length 3.2
  Bottom Layer w0.6: R49.1 62.106,112.106 62.325,112.325 Q32.1
NetQ33_1: Q33.1 R46.2 | length 3.7
  Bottom Layer w0.6: R46.2 88.106,103.356 88.75,104 Q33.1
NetQ33_3: Q33.3 R54.2 | length 2.1
  Bottom Layer w0.6: R54.2 86.75,109.125 Q33.3
NetQ34_1: Q34.1 R47.2 | length 3.4
  Bottom Layer w0.6: R47.2 66.106,103.356 66.825,104.075 Q34.1
NetQ34_3: Q34.3 R55.2 | length 2
  Bottom Layer w0.6: R55.2 65.075,108.881 Q34.3
NetQ35_1: Q35.1 R54.1 | length 3.2
  Bottom Layer w0.6: R54.1 88.106,112.106 88.75,112.75 Q35.1
NetQ36_1: Q36.1 R55.1 | length 3
  Bottom Layer w0.6: R55.1 66.356,112.106 66.825,112.575 Q36.1
NetQ37_1: Q37.1 R52.2 | length 3.6
  Bottom Layer w0.6: R52.2 92.856,103.356 93.75,104.25 Q37.1
NetQ37_3: Q37.3 R60.2 | length 2.1
  Bottom Layer w0.6: R60.2 91.75,109.125 Q37.3
NetQ38_1: Q38.1 R53.2 | length 3.3
  Bottom Layer w0.6: R53.2 70.606,103.356 71.5,104.25 Q38.1
NetQ38_3: Q38.3 R61.2 | length 2
  Bottom Layer w0.6: R61.2 69.75,108.881 Q38.3
NetQ39_1: Q39.1 R60.1 | length 3.2
  Bottom Layer w0.6: R60.1 93.106,112.106 93.75,112.75 Q39.1
NetQ40_1: Q40.1 R61.1 | length 3.1
  Bottom Layer w0.6: R61.1 71.106,112.106 71.5,112.5 Q40.1
NetQ41_1: Q41.1 R57.2 | length 2.3
  Top Layer w0.6: R57.2 95.781,97.75 Q41.1
NetQ41_3: Q41.3 R64.2 | length 2.2
  Top Layer w0.6: Q41.3 R64.2
NetQ42_1: Q42.1 R59.2 | length 3.6
  Bottom Layer w0.6: R59.2 97.606,103.356 98.55,104.3 Q42.1
NetQ42_3: Q42.3 R67.2 | length 2.1
  Bottom Layer w0.6: R67.2 96.55,109.125 Q42.3
NetQ43_1: Q43.1 R64.1 | length 2.2
  Top Layer w0.6: R64.1 104.881,97.75 Q43.1
NetQ44_1: Q44.1 R67.1 | length 3.1
  Bottom Layer w0.6: R67.1 97.856,112.106 98.55,112.8 Q44.1
NetQ45_1: Q45.1 R63.2 | length 2.3
  Top Layer w0.6: R63.2 95.781,93.35 Q45.1
NetQ45_3: Q45.3 R72.2 | length 2.2
  Top Layer w0.6: Q45.3 R72.2
NetQ46_1: Q46.1 R66.2 | length 3.7
  Bottom Layer w0.6: R66.2 102.606,103.356 103.25,104 Q46.1
NetQ46_3: Q46.3 R73.2 | length 2.1
  Bottom Layer w0.6: R73.2 101.25,109.125 Q46.3
NetQ47_1: Q47.1 R72.1 | length 2.2
  Top Layer w0.6: R72.1 104.881,93.35 Q47.1
NetQ48_1: Q48.1 R73.1 | length 3.3
  Bottom Layer w0.6: R73.1 102.856,112.106 103.25,112.5 Q48.1
NetQ49_1: Q49.1 R70.2 | length 2.3
  Top Layer w0.6: R70.2 95.781,88.95 Q49.1
NetQ49_3: Q49.3 R78.2 | length 2.2
  Top Layer w0.6: Q49.3 R78.2
NetQ50_1: Q50.1 R71.2 | length 3.7
  Bottom Layer w0.6: R71.2 107.106,103.356 107.75,104 Q50.1
NetQ50_3: Q50.3 R79.2 | length 2.1
  Bottom Layer w0.6: R79.2 105.75,109.125 Q50.3
NetQ51_1: Q51.1 R78.1 | length 2.2
  Top Layer w0.6: R78.1 104.881,88.95 Q51.1
NetQ52_1: Q52.1 R79.1 | length 3.3
  Bottom Layer w0.6: R79.1 107.356,112.106 107.75,112.5 Q52.1
NetQ53_1: Q53.1 R76.2 | length 2.3
  Top Layer w0.6: R76.2 95.781,84.45 Q53.1
NetQ53_3: Q53.3 R84.2 | length 2.2
  Top Layer w0.6: Q53.3 R84.2
NetQ54_1: Q54.1 R77.2 | length 3.7
  Bottom Layer w0.6: R77.2 111.856,103.356 112.55,104.05 Q54.1
NetQ54_3: Q54.3 R85.2 | length 2.1
  Bottom Layer w0.6: R85.2 110.55,109.125 Q54.3
NetQ55_1: Q55.1 R84.1 | length 2.2
  Top Layer w0.6: R84.1 104.881,84.45 Q55.1
NetQ56_1: Q56.1 R85.1 | length 3.3
  Bottom Layer w0.6: R85.1 112.106,112.106 112.55,112.55 Q56.1
NetQ58_1: Q58.1 R83.2 | length 2.3
  Top Layer w0.6: R83.2 95.781,79.85 Q58.1
NetQ58_3: Q58.3 R91.2 | length 2.2
  Top Layer w0.6: Q58.3 R91.2
NetQ60_1: Q60.1 R91.1 | length 2.2
  Top Layer w0.6: R91.1 104.881,79.85 Q60.1
NetQ62_1: Q62.1 R90.2 | length 2.3
  Top Layer w0.6: R90.2 95.781,75.45 Q62.1
NetQ62_3: Q62.3 R97.2 | length 2.2
  Top Layer w0.6: Q62.3 R97.2
NetQ64_1: Q64.1 R97.1 | length 2.2
  Top Layer w0.6: R97.1 104.881,75.45 Q64.1
NetQ66_1: Q66.1 R95.2 | length 2.3
  Top Layer w0.6: R95.2 95.781,71.05 Q66.1
NetQ66_3: Q66.3 R103.2 | length 2.2
  Top Layer w0.6: Q66.3 R103.2
NetQ68_1: Q68.1 R103.1 | length 2.2
  Top Layer w0.6: R103.1 104.881,71.05 Q68.1
NetQ70_1: Q70.1 R101.2 | length 2.3
  Top Layer w0.6: R101.2 95.781,66.55 Q70.1
NetQ70_3: Q70.3 R108.2 | length 2.2
  Top Layer w0.6: Q70.3 R108.2
NetQ72_1: Q72.1 R108.1 | length 2.2
  Top Layer w0.6: R108.1 104.881,66.55 Q72.1
NetU1_9: U1.9 U2.14 | length 61.2
  Top Layer w0.6: v1(62.9,67.74) 65.2,70.04 65.2,86 66.3,87.1 v1@70,87.1
  Bottom Layer w0.4: U1.9 68.965,85.805 v1(70.2,87.04)
  Bottom Layer w0.6: U2.14 52.795,69.695 51.9,68.8 51.9,67.2 54.2,64.9 55.9,64.9 56.7,65.7 56.7,66.8 57.4,67.5 v1@62.1,67.5
NetU2_9: U2.9 U3.14 | length 83.1
  Top Layer w0.6: v1(62.1,72.96) 64.1,74.96 64.1,93 64.8,93.7 71,93.7 71.6,94.3 71.6,96.5 74.4,99.3 83.9,99.3 v1(86.1,97.1)
  Bottom Layer w0.6: U2.9 59.145,86.645 57.1,84.6 57.1,71.7 57.6,71.2 60.6,71.2 61.5,72.1 ; v1(86.1,97.1) 88.6,94.6 88.6,92.6 90.3,90.9 92.3,90.9 93.395,89.805 U3.14
NetU3_9: U3.9 U4.14 | length 44.9
  Top Layer w0.6: v1@82.4,72.84 82.94,72.3 v1(94.3,72.3)
  Bottom Layer w0.6: U4.14 82.08,83.02 82.8,82.3 82.8,73.9 82.5,73.6 v1(82.5,72.3) ; v1(94.3,72.3) 96.8,72.3 99.745,75.245 U3.9
U1_A: R2.1 U1.15 | length 24
  Top Layer w0.6: R2.1 v1(58.9,65.6)
  Bottom Layer w0.6: v1(58.9,65.6) 64.7,65.6 65.8,66.7 65.8,77.7 66.285,78.185 U1.15
U1_B: R3.1 U1.1 | length 16.2
  Top Layer w0.6: R3.1 58.08,70.1 v1(58.9,69.28)
  Bottom Layer w0.6: v1(58.9,69.28) 61.68,69.28 64.3,71.9 64.3,76.9 64.285,76.915 U1.1
U1_C: R6.1 U1.2 | length 11.5
  Top Layer w0.6: R6.1 57.36,74.5 v1(58.9,72.96)
  Bottom Layer w0.6: v1(58.9,72.96) 61.1,75.16 61.1,77.2 62.085,78.185 U1.2
U1_D: R9.1 U1.3 | length 9.7
  Top Layer w0.6: R9.1 56.64,78.9 v1(58.9,76.64)
  Bottom Layer w0.6: v1(58.9,76.64) 58.9,76.8 61.555,79.455 U1.3
U1_E: R13.1 U1.4 | length 9
  Top Layer w0.6: R13.1 55.72,83.5 v1(58.9,80.32)
  Bottom Layer w0.6: v1(58.9,80.32) 59.305,80.725 U1.4
U1_F: R18.1 U1.5 | length 10.4
  Top Layer w0.6: R18.1 57.7,85.981 57.7,85.3 v1(58.9,84.1)
  Bottom Layer w0.6: v1(58.9,84.1) 59.1,84.1 61.205,81.995 U1.5
U1_G: R23.1 U1.6 | length 16.1
  Top Layer w0.6: R23.1 58.4,92.4 v1(62,88.8)
  Bottom Layer w0.6: v1(62,88.8) 60.2,87 60.2,85.063 60.5,84.763 60.5,84.7 61.935,83.265 U1.6
U1_H: R29.1 U1.7 | length 19.2
  Top Layer w0.6: R29.1 56.9,96.8 v1(62.1,91.6)
  Bottom Layer w0.6: v1(62.1,91.6) 63.8,89.9 63.8,88.1 62.8,87.1 62.1,87.1 61.2,86.2 61.2,85.6 62.265,84.535 U1.7
U2_A: R11.1 U2.15 | length 20.2
  Bottom Layer w0.6: R11.1 48.244,90.5 50.75,90.5 51.525,89.725 U2.15
U2_B: R15.1 U2.1 | length 12.4
  Bottom Layer w0.6: R15.1 47.494,95.75 49,95.75 50.255,94.495 U2.1
U2_C: R22.1 U2.2 | length 10.2
  Bottom Layer w0.6: R22.1 46.8,99.7 51.525,94.975 U2.2
U2_D: R28.1 U2.3 | length 8.8
  Bottom Layer w0.6: R28.1 51.3,97.45 52.795,95.955 U2.3
U2_E: R35.1 U2.4 | length 9
  Bottom Layer w0.6: U2.4 54.065,97.815 56.05,99.8 R35.1
U2_F: R42.1 U2.5 | length 10.4
  Bottom Layer w0.6: U2.5 55.335,95.754 R42.1
U2_G: R47.1 U2.6 | length 13.2
  Bottom Layer w0.6: U2.6 56.605,95.105 59.25,97.75 61.831,97.75 R47.1
U2_H: R53.1 U2.7 | length 16.3
  Bottom Layer w0.6: U2.7 57.875,94.625 59.5,96.25 63,96.25 67.744,100.994 R53.1
U3_A: R33.1 U3.15 | length 21.8
  Bottom Layer w0.6: R33.1 79.106,100.994 87.7,92.4 87.7,91.2 87.9,91 88.673,91 89.873,89.8 91.7,89.8 92.125,89.375 U3.15
U3_B: R39.1 U3.1 | length 13.7
  Bottom Layer w0.6: R39.1 83.594,99.4 86.8,99.4 90.855,95.345 U3.1
U3_C: R46.1 U3.2 | length 10.4
  Bottom Layer w0.6: R46.1 92.125,95.619 U3.2
U3_D: R52.1 U3.3 | length 8.9
  Bottom Layer w0.6: R52.1 91.75,97.75 93.395,96.105 U3.3
U3_E: R59.1 U3.4 | length 9
  Bottom Layer w0.6: U3.4 94.665,95.915 96.55,97.8 R59.1
U3_F: R66.1 U3.5 | length 10.4
  Bottom Layer w0.6: U3.5 95.935,95.435 101.25,100.75 R66.1
U3_G: R71.1 U3.6 | length 13.2
  Bottom Layer w0.6: U3.6 97.205,94.955 99.5,97.25 102.006,97.25 R71.1
U3_H: R77.1 U3.7 | length 16.5
  Bottom Layer w0.6: U3.7 98.475,94.475 100.25,96.25 105.806,96.25 R77.1
U4_A: R57.1 U4.15 | length 20.6
  Top Layer w0.6: v1(84.8,91) 88.3,91 92.469,95.169 R57.1
  Bottom Layer w0.6: U4.15 81.29,84.29 82.2,85.2 82.2,88.4 v1(84.8,91)
U4_B: R63.1 U4.1 | length 11.7
  Top Layer w0.6: v1@84.9,88.5 86.3,89.9 89.969,89.9 R63.1
  Bottom Layer w0.6: U4.1 84.7,87.9 v1(84.8,88)
U4_C: R70.1 U4.2 | length 10.8
  Top Layer w0.6: v1@88.4,88 R70.1
  Bottom Layer w0.6: U4.2 87.19,84.29 87.9,85 87.9,87.5 v1@88.4,88
  other v1: 87.9,88
U4_D: R76.1 U4.3 | length 8
  Top Layer w0.6: v1(90.3,83.44) 90.36,83.5 R76.1
  Bottom Layer w0.6: U4.3 88.82,83.02 89.24,83.44 v1(90.3,83.44)
U4_E: R83.1 U4.4 | length 9.6
  Top Layer w0.6: v1(90.3,78.94) 90.34,78.9 R83.1
  Bottom Layer w0.6: U4.4 88.65,81.75 90.3,80.1 v1(90.3,78.94)
U4_F: R90.1 U4.5 | length 12.1
  Top Layer w0.6: v1(90.3,74.44) 90.36,74.5 R90.1
  Bottom Layer w0.6: U4.5 87.42,80.48 88.4,79.5 88.4,78.2 90.3,76.3 v1(90.3,74.44)
U4_G: R95.1 U4.6 | length 16.9
  Top Layer w0.6: v1(90.3,69.94) 90.46,70.1 R95.1
  Bottom Layer w0.6: U4.6 86.39,79.21 87.2,78.4 87.2,78.1 87.7,77.6 87.7,75.5 86.9,74.7 86.9,70.9 87.86,69.94 v1(90.3,69.94)
U4_H: R101.1 U4.7 | length 18.2
  Top Layer w0.6: v1(90.3,65.44) 90.46,65.6 R101.1
  Bottom Layer w0.6: U4.7 85.76,77.94 86.5,77.2 86.5,76.1 85.9,75.5 85.9,69.84 v1(90.3,65.44)
VCC: P1.4 U1.16 U2.16 U3.16 U4.16 | length 92.4
  Top Layer w0.6: v1(68,74.6) 68.3,74.6 68,74.9 68,79.5 74.31,85.81 P1.4
  Bottom Layer w0.6: U2.16 50.255,66.945 53.9,63.3 65,63.3 68,66.3 U1.16 ; P1.4 75.25,85.56 U4.16 79.9,91.1 82,93.2 85.4,93.2 86.7,91.9 86.7,90.6 87.3,90 88.4,90 90.4,88 U3.16
pads on no net: U4.9

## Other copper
Top Layer:
  text "TOP" at 28.5,117.1 h6
Bottom Layer:
  text "Bottom" at 46.2,86.7 h6 r90

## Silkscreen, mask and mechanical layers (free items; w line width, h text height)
Mechanical 1:
  the board outline again, w0.2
